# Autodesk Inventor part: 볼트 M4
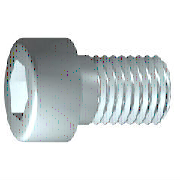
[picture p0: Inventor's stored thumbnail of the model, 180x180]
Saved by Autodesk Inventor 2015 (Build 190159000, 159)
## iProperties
Created: 2012-02
Part Number: 볼트 M4
Material: 스테인리스강
Description: 6각 소켓 머리 캡 나사
Document SubType Name: Modeling
Standard: ISO 4762
Designer: mduedu
Standard Revision: Fourth edition 2004-03-01
Standards Organization: ISO
Language: ko-KR
Size Designation: M4 x 16
Categories: <MemberInstance><Categories><Category DisplayName="조임쇠" InternalName="e4da775c-781d-43d5-af7c-5136215cf5a6" Mnemonic="FSTN"><Category DisplayName="볼트" InternalN
Density: 7.75 g/cm^3
Appearance: 반광택
IsCustomPart: 0
Author: mduedu
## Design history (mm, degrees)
sketch "스케치1"
  geometry: L1 (-1, 0)-(16, 0); L2 (16, 0)-(16, 2); L3 (16, 2)-(1.75, 2); L4 (1.75, 2)-(1.32, 2); L5 (1.32, 2)-(0, 2); L6 (0, 2)-(0, 3.5); L7 (0, 3.5)-(-4, 3.5); L8 (-4, 3.5)-(-4, 1.732); L9 (-4, 1.732)-(-2, 1.732); L10 (-2, 1.732)-(-1, 0); L11 (-8, 0)-(20, 0) reference; L12 (0, -0.7)-(0, 4.2) reference; L13 (1.75, 2)-(0, 2)
  constraints: 22 end point, 6 parallel, 2 collinear, 2 perpendicular, 1 horizontal, 1 point on line
  dimensions: "d1" = 14.25 distance from line of L3.end L2 (= GEL); "d2" = 0.42952 distance of L4.end L3.end (computed from GAL); "d3" = 4 distance between parallel lines of L8 L6 (= KOH); "d4" = 2 distance of L8.end L9.end (= INTI); "d5" = 60 deg angle of L10 L1; "d6" = 4 diameter of L3 L1 (= GD); "d7" = 4 diameter of L5 L1 (= BDM); "d8" = 3.4641 diameter of L9 L1 (= 1.1547 x SW); "d9" = 7 diameter of L7 L1 (= KOD); "d26" = 16 distance between parallel lines of L12 L2 (= NLG)
revolve "본체" sketch "스케치1" stored, may be unused: angle "d10" = 90 deg
sketch "스케치2"
  geometry: L1 (0, -4.9)-(0, 4.9) reference; L2 (-4.9, 0)-(4.9, 0) reference; L3 (1.732, 0)-(0.866, -1.5); L4 (0.866, -1.5)-(-0.866, -1.5); L5 (-0.866, -1.5)-(-1.732, 0); L6 (-1.732, 0)-(-0.866, 1.5); L7 (-0.866, 1.5)-(0.866, 1.5); L8 (0.866, 1.5)-(1.732, 0); 2 further points
  constraints: 12 end point, 1 coincident, 1 horizontal alignment, 1 point on line, 12 other
extrude "슬롯" join sketch "스케치2" stored distance "d11" = 10; taper "d12" = 0 deg
workplane "Work Plane1"
fillet "Fillet2" dims "d30" = 0.1 (= R)
body "Solid1"
fillet "모깎기1" dims "d17" = 0.4 (= RR)
feature "스레드" dims "d13" = 14.25 (= GEL), "d14" = 0
chamfer "모따기1" distance "d15" = 0.42941 (= -0.5 x SPD + 0.5 x GD); stored, may be unused: second distance "d16" = 0.42941 (= GUL), angle "d27" = 45 deg
other parameters: "GD" = 4 [user parameter; used in 2 equation terms], "NLG" = 16 [user parameter; used in 1 equation term], "GEL" = 14.25 [user parameter; used in 2 equation terms], "KOD" = 7 [user parameter; used in 1 equation term], "KOH" = 4 [user parameter; used in 1 equation term], "INTI" = 2 [user parameter; used in 1 equation term], "GAL" = 0.42941 (= 0.61345 x PTC) [user parameter; used in 1 equation term], "GUL" = 0.42941 (= 0.61345 x PTC) [user parameter; used in 1 equation term], "BDM" = 4 (= NND) [user parameter; used in 1 equation term], "SW" = 3 [user parameter; used in 2 equation terms], "RR" = 0.4 [user parameter; used in 1 equation term], "SPD" = 3.14117 (= NND - 1.2269 x PTC) [user parameter; used in 1 equation term], "d19" = 0, "d28" = 0, "d29" = 0, "R" = 0.1 [user parameter; used in 1 equation term], "TOA" = 30 deg [user parameter], "GD1" = 3.14117 (= THREADDIA - 1.2269 x PTC) [user parameter], "THREADDIA" = 4 [user parameter; used in 1 equation term], "FAWI" = 45 deg [user parameter], "TPU" = 14.28571 (computed from PTC) [user parameter], "PTC" = 0.7 [user parameter; used in 5 equation terms], "NND" = 4 [user parameter; used in 2 equation terms], "E0" = 3.465 (= 1.155 x SW) [user parameter]
